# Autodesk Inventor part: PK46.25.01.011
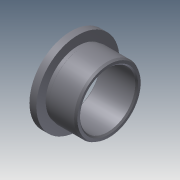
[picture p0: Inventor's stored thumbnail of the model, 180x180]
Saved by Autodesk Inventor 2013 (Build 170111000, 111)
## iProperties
Created: 2005-04
Part Number: PK46.25.01.011
Material: Steel, Mild
Document SubType Name: Modeling
Designer: salex
Manufacturer: Standard
Standards Organization: Custom
Density: 7.86 g/cm^3
Author: salex
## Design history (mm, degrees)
sketch "Эскиз1"
  geometry: L1 (0, 0)-(56.407, 0); L2 (0, 40)-(0, 60); L3 (0, 60)-(10, 60); L4 (10, 60)-(10, 46.5); L5 (10, 46.5)-(15, 46.5); L6 (15, 46.5)-(16, 47.5); L7 (16, 47.5)-(55, 47.5); L8 (55, 47.5)-(55, 40); L9 (55, 40)-(0, 40)
  constraints: 18 end point, 5 parallel, 2 perpendicular, 1 horizontal, 1 other
  dimensions: "d0" = 0 distance from line of L1.start L2; "d1" = 10 distance of L2.end L3.end; "d2" = 5 distance of L4.end L5.end; "d3" = 45 deg angle of L6 L5; "d4" = 55 distance between parallel lines of L8 L2; "d5" = 80 diameter of L9 L1; "d6" = 120 diameter of L3 L1; "d7" = 95 diameter of L7 L1; "d8" = 93 diameter of L5 L1
revolve "Вращение1" sketch "Эскиз1" stored, may be unused: angle "d9" = 90 deg
chamfer "Фаска1" distance "d10" = 2; stored, may be unused: second distance "d11" = 2, angle "d12" = 45 deg
chamfer "Фаска2" distance "d13" = 3; stored, may be unused: second distance "d14" = 2, angle "d15" = 30 deg
body "Solid1"
